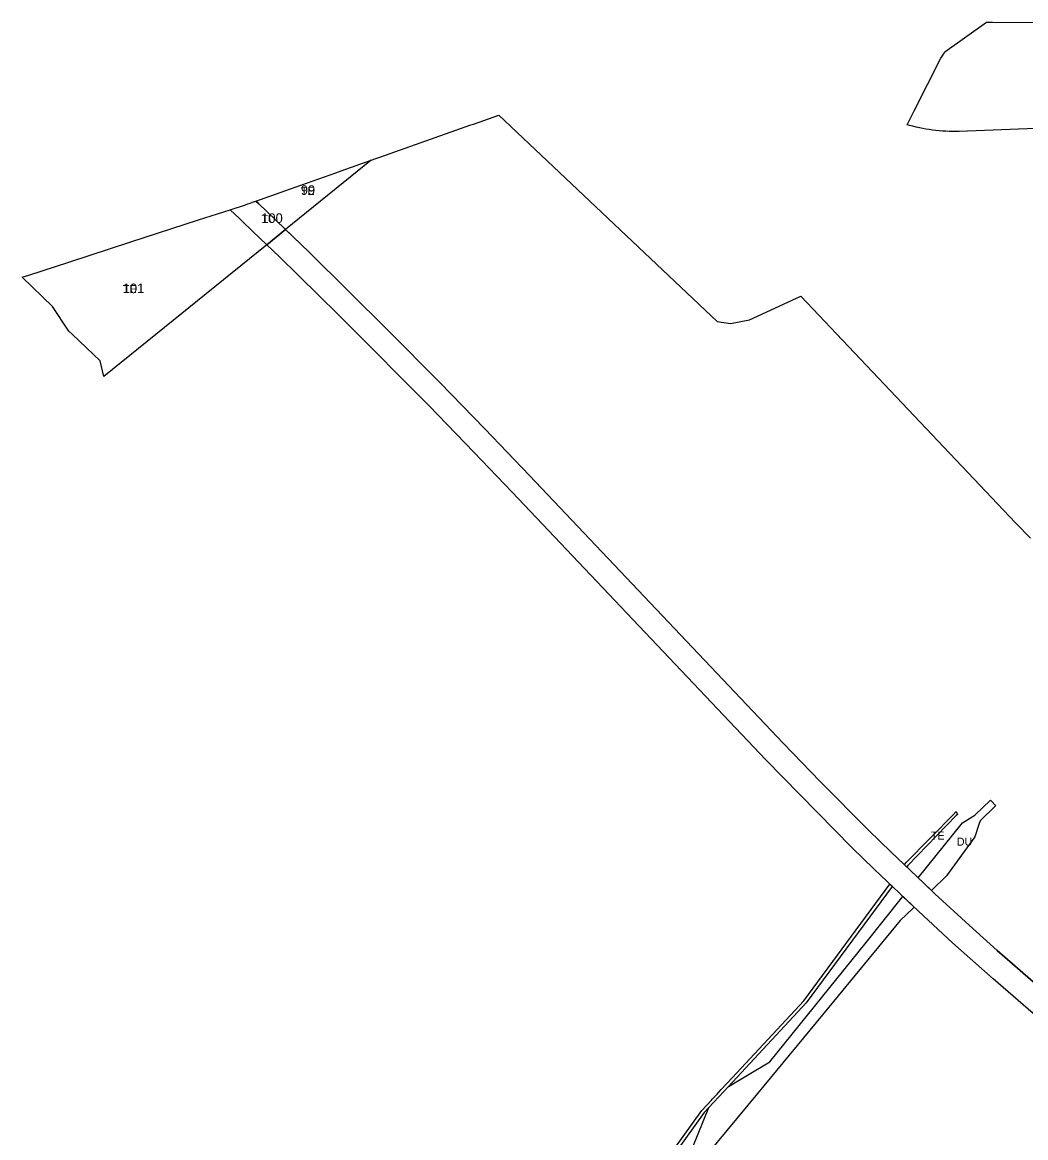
# Model space of a CAD drawing. Extents: x -545758 to -541641, y -1153152 to -1149975.
# Drawn here: x -543661 to -543035, y -1150683 to -1149986 of the extents above; entities that cross this region are included whole.
import ezdxf

# ---------------------------------------------------------------- set-up
doc = ezdxf.new("R2010")
doc.units = 0
for name, color, linetype in [('90310013', 7, 'Continuous'), ('90350033', 7, 'Continuous'), ('90380023', 7, 'Continuous'), ('90400013', 7, 'Continuous'), ('90400023', 7, 'Continuous'), ('ID_navrh', 7, 'Continuous')]:
    doc.layers.add(name, color=color, linetype=linetype)

msp = doc.modelspace()

# ---------------------------------------------------------------- linework, layer by layer
at = {"layer": '90310013'}
msp.add_lwpolyline([(-543098.262, -1150523.64), (-543101.822, -1150520.244), (-543074.08, -1150485.82), (-543069.043, -1150482.66), (-543066.46, -1150481.04), (-543056.63, -1150471.65), (-543056.04, -1150472.29), (-543053.95, -1150474.59), (-543053.37, -1150475.24), (-543063.12, -1150484.56), (-543063.887, -1150486.947), (-543066.32, -1150494.52), (-543084.05, -1150518.91), (-543093.514, -1150528.088)], close=True, dxfattribs=at)
msp.add_lwpolyline([(-543245.84, -1150696.55), (-543232.51, -1150663.7), (-543229.59, -1150660.58), (-543226.01, -1150656.76), (-543223.33, -1150653.9), (-543220.18, -1150650.51), (-543194.48, -1150635.21), (-543134.28, -1150560.52), (-543111.232, -1150531.92), (-543104.271, -1150538.531), (-543104.97, -1150539.21), (-543112.93, -1150546.93), (-543157.53, -1150600.92), (-543202.13, -1150654.9), (-543240.31, -1150701.11)], dxfattribs=at)
at = {"layer": '90350033'}
msp.add_lwpolyline([(-543023.498, -1150590.698), (-543037.995, -1150578.194), (-543052.36, -1150565.571), (-543069.987, -1150549.764), (-543091.287, -1150530.174), (-543098.262, -1150523.64), (-543118.844, -1150504.007), (-543132.527, -1150490.655), (-543162.992, -1150460.034), (-543186.011, -1150436.046), (-543344.484, -1150268.967), (-543372.384, -1150239.793), (-543400.503, -1150210.87), (-543432.945, -1150178.086), (-543457.476, -1150153.701), (-543482.186, -1150129.482), (-543502.907, -1150109.435), (-543513.746, -1150099.042), (-543515.367, -1150097.492), (-543497.19, -1150091.06), (-543479.54, -1150084.81), (-543465.48, -1150079.83), (-543462.07, -1150078.62), (-543440.48, -1150070.98), (-543438.05, -1150070.12), (-543381.13, -1150049.97), (-543379.5, -1150049.39), (-543363.67, -1150043.79), (-543227.35, -1150172.67), (-543219.01, -1150174.06), (-543207.09, -1150171.73), (-543175.045, -1150156.983), (-543040.909, -1150298.404), (-543037.677, -1150301.811), (-543034.668, -1150304.977), (-543031.686, -1150308.099)], dxfattribs=at)
at = {"layer": '90380023'}
msp.add_lwpolyline([(-543525.596, -1150108.465), (-543531.426, -1150102.892), (-543521.79, -1150099.76), (-543521.08, -1150099.51), (-543518.85, -1150098.72), (-543517.79, -1150098.35), (-543517.672, -1150098.308), (-543517.585, -1150098.277), (-543515.367, -1150097.492), (-543513.746, -1150099.042), (-543502.907, -1150109.435), (-543496.832, -1150115.312), (-543508.577, -1150124.819), (-543517.46, -1150116.254), (-543524.117, -1150109.88)], close=True, dxfattribs=at)
msp.add_lwpolyline([(-543029.924, -1150604.876), (-543054.91, -1150583.328), (-543080.232, -1150560.722), (-543101.53, -1150541.133), (-543129.247, -1150514.814), (-543143.124, -1150501.272), (-543196.816, -1150446.451), (-543355.349, -1150279.309), (-543379.192, -1150254.349), (-543407.21, -1150225.461), (-543423.305, -1150209.081), (-543443.557, -1150188.687), (-543463.914, -1150168.427), (-543500.913, -1150132.207), (-543508.577, -1150124.819), (-543496.832, -1150115.312), (-543482.186, -1150129.482), (-543457.476, -1150153.701), (-543432.945, -1150178.086), (-543400.503, -1150210.87), (-543372.384, -1150239.793), (-543344.484, -1150268.967), (-543186.011, -1150436.046), (-543162.992, -1150460.034), (-543132.527, -1150490.655), (-543118.844, -1150504.007), (-543098.262, -1150523.64), (-543091.287, -1150530.174), (-543069.987, -1150549.764), (-543052.36, -1150565.571), (-543037.995, -1150578.194), (-543023.498, -1150590.698)], dxfattribs=at)
at = {"layer": '90400013'}
msp.add_lwpolyline([(-543108.935, -1150513.459), (-543110.38, -1150512.08), (-543109.47, -1150510.9), (-543079.12, -1150479.93), (-543078.97, -1150479.78), (-543077.94, -1150478.69), (-543077.28, -1150480.58), (-543077.98, -1150481.28), (-543108.19, -1150512.45)], close=True, dxfattribs=at)
msp.add_lwpolyline([(-543295.21, -1150746.65), (-543236.92, -1150665.47), (-543230.9, -1150659.05), (-543230.42, -1150658.54), (-543227.37, -1150655.29), (-543226.31, -1150654.16), (-543226.31, -1150654.16), (-543224.74, -1150652.49), (-543217.86, -1150645.08), (-543173.2, -1150597.05), (-543119.365, -1150524.197), (-543117.9, -1150525.589), (-543171.65, -1150598.32), (-543220.18, -1150650.51), (-543223.33, -1150653.9), (-543226.01, -1150656.76), (-543229.59, -1150660.58), (-543232.51, -1150663.7), (-543235.36, -1150666.74), (-543293.65, -1150747.91)], dxfattribs=at)
at = {"layer": '90400023'}
msp.add_lwpolyline([(-542980.889, -1150050.388), (-543076.08, -1150053.95), (-543078.154, -1150054.006), (-543080.232, -1150054.02), (-543082.315, -1150053.99), (-543084.399, -1150053.918), (-543086.484, -1150053.802), (-543088.568, -1150053.643), (-543090.65, -1150053.44), (-543092.729, -1150053.194), (-543094.803, -1150052.905), (-543096.872, -1150052.573), (-543098.933, -1150052.197), (-543100.985, -1150051.779), (-543103.027, -1150051.319), (-543105.058, -1150050.817), (-543107.077, -1150050.273), (-543108.581, -1150049.834), (-543104.22, -1150041.2), (-543087.59, -1150008.28), (-543085.86, -1150005.67), (-543085.02, -1150004.39), (-543059.12, -1149985.85), (-543055.32, -1149985.86), (-543004.7, -1149986.01)], dxfattribs=at)
for points in [[(-543443.298, -1150071.977), (-543496.832, -1150115.312), (-543502.907, -1150109.435), (-543513.746, -1150099.042), (-543515.367, -1150097.492), (-543515.367, -1150097.492), (-543497.19, -1150091.06), (-543479.54, -1150084.81), (-543465.48, -1150079.83), (-543462.07, -1150078.62)], [(-543551.17, -1150109.31), (-543531.426, -1150102.892), (-543531.426, -1150102.892), (-543525.596, -1150108.465), (-543524.117, -1150109.88), (-543517.46, -1150116.254), (-543508.577, -1150124.819), (-543610.301, -1150207.162), (-543612.7, -1150197.25), (-543629.86, -1150180.92), (-543632.15, -1150178.74), (-543642.4, -1150163.35), (-543661.23, -1150145.1), (-543657.21, -1150143.79), (-543632.2, -1150135.66), (-543593.45, -1150123.06)]]:
    msp.add_lwpolyline(points, close=True, dxfattribs=at)

# ---------------------------------------------------------------- texts
at = {"layer": '90310013'}
msp.add_text('DU', height=5, rotation=360, dxfattribs=at).set_placement((-543077.596, -1150500.107))
at = {"layer": '90380023'}
msp.add_text('TU', height=5, rotation=360, dxfattribs=at).set_placement((-543511.957, -1150111.155))
at = {"layer": '90400013'}
msp.add_text('TE', height=5, rotation=360, dxfattribs=at).set_placement((-543093.83, -1150496.287))
at = {"layer": '90400023'}
for p in [(-543487.279, -1150093.644), (-543598.441, -1150155.027)]:
    msp.add_text('TE', height=5, rotation=360, dxfattribs=at).set_placement(p)
at = {"layer": 'ID_navrh'}
for s, rotation, p in [('99', 0, (-543487.279, -1150093.644)), ('100', 360, (-543511.957, -1150111.155)), ('101', 0, (-543598.441, -1150155.027))]:
    msp.add_text(s, height=6, rotation=rotation, dxfattribs=at).set_placement(p)

doc.saveas('drawing.dxf')
